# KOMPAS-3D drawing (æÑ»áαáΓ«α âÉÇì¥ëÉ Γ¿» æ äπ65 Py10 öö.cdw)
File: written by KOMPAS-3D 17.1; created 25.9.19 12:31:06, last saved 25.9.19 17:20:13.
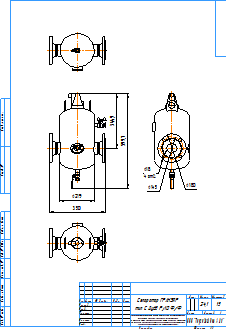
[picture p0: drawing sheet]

Sheet 1: A3, portrait

Title block, sheet 1: name: Сепаратор ГРАНЭЙР / тип С Ду65 Py10 Ф/Ф; material: Сталь 10  ГОСТ 1050-2013; mass: 24,1; sheets: 1; sheet format: A3; stored path: C:\Users\kka\KOMPAS_Work\!Trash\Сепаратор ГРАНЭЙР тип С Py10 ФФ\KOMPAS 2D\Сепаратор ГРАНЭЙР тип С Ду65 Py10 ФФ.cdw

Views: Проекционный вид 2, Проекционный вид 3, Проекционный вид 4
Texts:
  kka
  adl
  Рама для чертежей
  Лит-Масса-Масштаб
  Материал-Предприятие
  Масштаб
  Изм.
  Лист
  № докум.
  Подп.
  Дата
  Лит.
  Разраб.
  Пров.
  Т.контр.
  Листов
  Внимание! Данный продукт является объектом авторского права ООО «Торговый Дом АДЛ».
  Запрещается изменение, копирование, распространение
  (в том числе путем копирования на другие сайты и ресурсы в Интернете)
  или любое иное использование информации и объектов без предварительного
  согласия правообладателя (ООО «Торговый Дом АДЛ»).
  Н.контр.
  Утв.
  ООО "Торговый дом АДЛ"
  Изменение
  Номер документа
  Подпись
  Обозначение документа
  Наименование изделия
  Масса изделия по ГОСТ 2.109-73
  Порядковый номер листа
  Общее количество листов в документе
  Характер работы, выполненной лицом, подписавшим документ
  Наименование или индекс предприятия, выпускающего документ
  Инв. № подл.
  Подп. и дата
  Взам. инв. №
  Инв. № дубл.
  Инвентарный номер подлинника по ГОСТ 2.501-68
  Подпись принявшего подлинник в отдел технической документации
  Инвентарный номер подлинника, взамен которого выпущен данный подлинник
  Инвентарный номер дубликата по ГОСТ 2.502-68
  Подпись принявшего дубликат в отдел технической документации
  Справ. №
  Перв. примен.
  Обозначение документа, взамен или на основании которого выпущен данный документ
  Обозначение документа, в котором впервые записан данный документ
  Подпись лица, копировавшего чертеж
  Обозначение формата листа
  !Рама для чертежа
Dimensions and other numbers on the sheet: 145; 18; 4 отв.; 180; 1:5; 1; 24,1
